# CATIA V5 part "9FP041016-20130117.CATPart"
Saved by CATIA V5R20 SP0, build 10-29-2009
Part number: 9FP041016-20130117
Revision: ANY
Definition: UNKNOWN
Nomenclature: 9FP041016-20130117
Source: Unknown
Bounding box of the stored display mesh (mm): x -8 to 8, y -8 to 8, z 0 to 8
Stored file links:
  C:\Users\Utente\Desktop\IO LAVORO\3D X SITO CF\CUMSA\3D files PF\PF 1042WB\9FP041016-20130117.CATPart
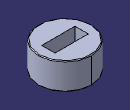
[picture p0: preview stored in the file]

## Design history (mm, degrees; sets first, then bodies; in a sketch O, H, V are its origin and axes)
Body1 "Chaflán1" (main body)
  Solid1: solid without history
